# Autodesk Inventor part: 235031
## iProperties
Created: 2006-08
Part Number: 235031
Material: 04 vz
Description: Sechskantmutter
Vendor: Autodesk Inc.
Document SubType Name: Modeling
Standard: DIN 439
Designer: I.Baliuc
Standards Organization: DIN
Language: de-DE
Size Designation: M8
Categories: <MemberInstance Version="R10.0.0"><Categories><Category DisplayName="Schrauben" InternalName="e4da775c-781d-43d5-af7c-5136215cf5a6" Mnemonic="FSTN"><Category Di
Density: 7.85 g/cm^3
Mass: 3.24841 g
Surface Area: 4.33744 cm^2
Volume: 0.41381 cm^3
Abmessung: M8
Author: T.Messerschmitt
Comments: DIN 439 - M8
Revision Number: 235031
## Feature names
1. Körper [Extrusion]
2. Fase1 [Revolution]
3. Gewinde [Hole]
4. Fase2 [Chamfer]
5. Fase3 [Chamfer]
